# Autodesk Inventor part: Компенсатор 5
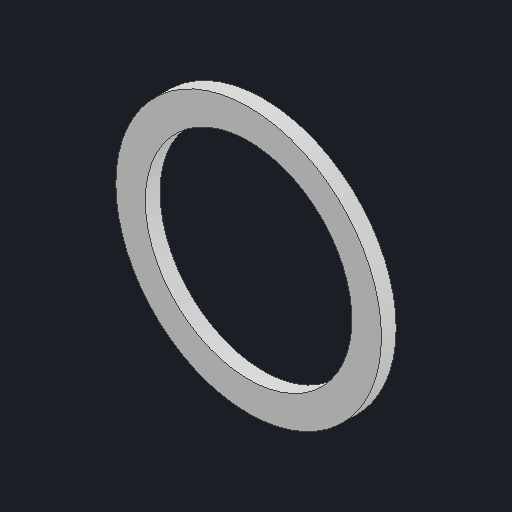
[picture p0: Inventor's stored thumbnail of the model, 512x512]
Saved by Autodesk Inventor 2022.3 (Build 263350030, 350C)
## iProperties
Created: 2020-09
Part Number: Компенсатор 5
Material: Типовые
Document SubType Name: Modeling
Designer: Карташов
Density: 1 g/cm^3
Appearance: По умолчанию
Title: D:\мои документы\Ирина\_WorldSkills\2020_09 ФНЧ\Module A\Участникам\GIVEN\Компенсатор 5.stp
Author: Дом
Sending System: Autodesk Inventor 2021
Preprocessor: ST-DEVELOPER v18.1
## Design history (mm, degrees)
feature "Твердое тело2"
node "Твердое тело1"
